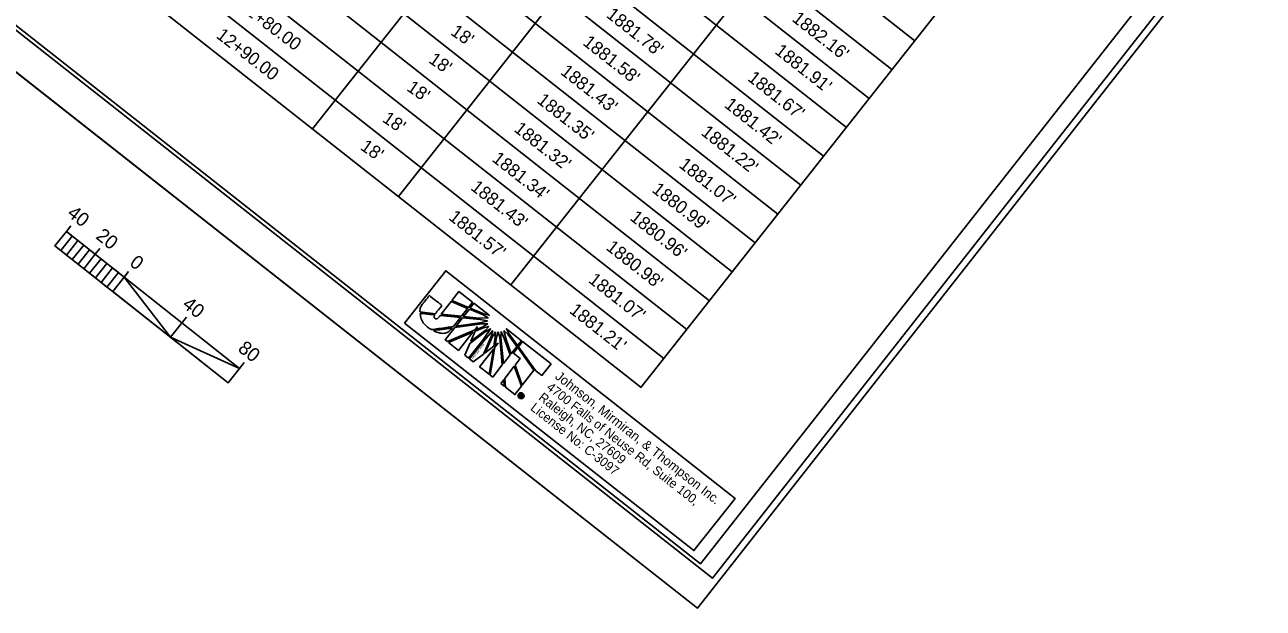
# Model space of a CAD drawing. Extents: x 556999 to 560450, y 504801 to 507732.
# Drawn here: x 557693 to 558366, y 506207 to 506524 of the extents above; entities that cross this region are included whole.
import ezdxf

# ---------------------------------------------------------------- set-up
doc = ezdxf.new("R2010")
doc.units = 0
for name, color, linetype in [('Prop Dimension', 7, 'Continuous'), ('Prop Horizontal Alignment Station Label', 7, 'Continuous'), ('Sheet Border Standard 30in CELL', 7, 'Continuous'), ('Sheet Cutting Line CELL', 7, 'Continuous'), ('Sheet Data Field CELL', 7, 'Continuous'), ('Sheet Plot Border Inside CELL', 7, 'Continuous'), ('Sheet Plot Border Outside CELL', 7, 'Continuous'), ('Sheet Title CELL', 7, 'Continuous')]:
    doc.layers.add(name, color=color, linetype=linetype)

msp = doc.modelspace()

# ---------------------------------------------------------------- linework, layer by layer
at = {"layer": 'Prop Dimension'}
for p, q in [((557928.5, 506379.09), (557924.67, 506374.2)), ((557935.87, 506373.31), (557928.5, 506379.09)), ((557924.23, 506373.64), (557918.84, 506366.78)), ((557933.22, 506369.93), (557924.23, 506373.64)), ((557924.67, 506374.2), (557933.64, 506370.46)), ((557933.64, 506370.46), (557935.87, 506373.31)), ((557936.66, 506372.74), (557934.59, 506370.1)), ((557944.95, 506366.24), (557936.66, 506372.74)), ((557918.84, 506366.78), (557929.87, 506365.66)), ((557930.51, 506364.9), (557926.91, 506360.31)), ((557929.87, 506365.66), (557933.22, 506369.93)), ((557940.08, 506363.95), (557930.51, 506364.9)), ((557934.14, 506369.53), (557931.02, 506365.55)), ((557931.02, 506365.55), (557939.29, 506364.71)), ((557941.65, 506366.39), (557934.14, 506369.53)), ((557934.59, 506370.1), (557942.1, 506366.96)), ((557939.29, 506364.71), (557944.29, 506364.79)), ((557944, 506363.17), (557940.08, 506363.95)), ((557944.29, 506364.79), (557941.65, 506366.39)), ((557942.1, 506366.96), (557944.95, 506366.24)), ((557926.3, 506359.53), (557921.05, 506352.85)), ((557922.26, 506351.89), (557936.82, 506358.05)), ((557935.99, 506356.99), (557922.84, 506351.45)), ((557941.01, 506361.65), (557926.3, 506359.53)), ((557926.91, 506360.31), (557941.01, 506362.3)), ((557928.33, 506347.14), (557935.99, 506356.99)), ((557942.79, 506357.28), (557934.47, 506350.96)), ((557935.03, 506352.17), (557942.71, 506358.02)), ((557937.32, 506357.52), (557935.03, 506352.17)), ((557936.82, 506358.05), (557938.34, 506359.99)), ((557941.77, 506359.41), (557937.32, 506357.52)), ((557938.34, 506359.99), (557937.66, 506358.37)), ((557937.66, 506358.37), (557941.4, 506359.97)), ((557941.01, 506362.3), (557944, 506363.17)), ((557944.15, 506361.62), (557941.01, 506361.65)), ((557941.4, 506359.97), (557944.15, 506361.62)), ((557941.41, 506352.79), (557945.65, 506358.85)), ((557944.7, 506360.13), (557941.77, 506359.41)), ((557946.87, 506357.9), (557941.93, 506352.38)), ((557942.71, 506358.02), (557944.7, 506360.13)), ((557945.65, 506358.85), (557942.79, 506357.28)), ((557945.99, 506354.78), (557946.87, 506357.9)), ((557948.3, 506357.3), (557946.7, 506354.75)), ((557948.26, 506354.31), (557948.3, 506357.3)), ((557949.86, 506357.14), (557948.91, 506354.07)), ((557950.64, 506354.09), (557949.86, 506357.14)), ((557951.42, 506357.35), (557951.25, 506354.2)), ((557953.15, 506353.69), (557951.42, 506357.35)), ((557952.96, 506357.98), (557954.07, 506353.03)), ((557955.01, 506355.91), (557952.96, 506357.98)), ((557962.47, 506352.43), (557954.33, 506358.87)), ((557954.33, 506358.87), (557955.63, 506356.28)), ((557921.05, 506352.85), (557922.26, 506351.89)), ((557922.84, 506351.45), (557928.33, 506347.14)), ((557934.47, 506350.96), (557931.69, 506344.56)), ((557933.7, 506342.98), (557941.41, 506352.79)), ((557941.93, 506352.38), (557934.23, 506342.57)), ((557941.76, 506345.04), (557945.99, 506354.78)), ((557946.7, 506354.75), (557942.77, 506345.82)), ((557947.46, 506349.36), (557948.26, 506354.31)), ((557949.72, 506351.07), (557948.03, 506348.92)), ((557948.91, 506354.07), (557948.19, 506349.9)), ((557948.19, 506349.9), (557949.72, 506351.07)), ((557952.02, 506339.22), (557950.64, 506354.09)), ((557951.25, 506354.2), (557952.62, 506339.99)), ((557956.32, 506344.7), (557953.15, 506353.69)), ((557954.07, 506353.03), (557956.84, 506345.36)), ((557959.95, 506349.22), (557955.01, 506355.91)), ((557955.63, 506356.28), (557960.39, 506349.78)), ((557960.39, 506349.78), (557962.47, 506352.43)), ((557963.07, 506352.02), (557960.84, 506349.17)), ((557978.55, 506339.87), (557963.07, 506352.02)), ((557931.69, 506344.56), (557933.7, 506342.98)), ((557936.27, 506340.96), (557941.76, 506345.04)), ((557947.2, 506347.86), (557939.68, 506338.28)), ((557942.77, 506345.82), (557947.46, 506349.36)), ((557944.96, 506334.14), (557947.2, 506347.86)), ((557948.03, 506348.92), (557945.53, 506333.63)), ((557952.62, 506339.99), (557956.32, 506344.7)), ((557956.84, 506345.36), (557959.95, 506349.22)), ((557960.39, 506348.6), (557958.06, 506345.64)), ((557958.06, 506345.64), (557961.84, 506342.67)), ((557960.43, 506348.65), (557960.39, 506348.6)), ((557969.28, 506336.44), (557960.43, 506348.65)), ((557960.84, 506349.17), (557960.77, 506349.09)), ((557960.77, 506349.09), (557970.28, 506336.11)), ((557934.23, 506342.57), (557936.27, 506340.96)), ((557939.68, 506338.28), (557944.96, 506334.14)), ((557946.84, 506332.61), (557952.02, 506339.22)), ((557958.59, 506338.53), (557953.42, 506331.94)), ((557962.45, 506327.74), (557958.59, 506338.53)), ((557961.84, 506342.67), (557959.06, 506339.13)), ((557959.06, 506339.13), (557962.9, 506328.31)), ((557973.57, 506333.52), (557978.55, 506339.87)), ((557945.53, 506333.63), (557946.84, 506332.61)), ((557952.86, 506331.22), (557951.23, 506329.16)), ((557953.14, 506327.66), (557952.86, 506331.22)), ((557953.42, 506331.94), (557953.87, 506327.09)), ((557962.9, 506328.31), (557969.28, 506336.44)), ((557970.28, 506336.11), (557973.57, 506333.52)), ((557951.23, 506329.16), (557953.14, 506327.66)), ((557953.87, 506327.09), (557958.87, 506323.17)), ((557958.87, 506323.17), (557962.45, 506327.74)), ((557961.35, 506322.34), (557962.23, 506323.47)), ((557962.23, 506323.47), (557962.69, 506323.11)), ((557962.69, 506323.11), (557962.53, 506322.89)), ((557962.53, 506322.89), (557962.69, 506323.11)), ((557962.69, 506323.11), (557962.77, 506323.05)), ((557963.22, 506323.77), (557963.03, 506323.54)), ((557963.03, 506323.54), (557963.22, 506323.77)), ((557961.47, 506321.54), (557961.27, 506321.29)), ((557961.27, 506321.29), (557961.47, 506321.54)), ((557961.28, 506321.29), (557961.27, 506321.29)), ((557961.61, 506322.14), (557961.35, 506322.34)), ((557961.47, 506321.54), (557961.48, 506321.53)), ((557961.95, 506322.58), (557961.61, 506322.14)), ((557962.16, 506322.42), (557961.95, 506322.58)), ((557962.32, 506323.05), (557962.11, 506322.79)), ((557962.11, 506322.79), (557962.32, 506322.62)), ((557962.32, 506322.62), (557962.16, 506322.42)), ((557962.16, 506322.42), (557962.32, 506322.62)), ((557962.17, 506322.41), (557962.16, 506322.42)), ((557962.53, 506322.89), (557962.32, 506323.05)), ((557962.32, 506322.62), (557962.33, 506322.62)), ((557962.56, 506322.87), (557962.53, 506322.89))]:
    msp.add_line(p, q, dxfattribs=at)
msp.add_lwpolyline([(557898.98, 506362.02), (558056.22, 506238.36), (558078.53, 506266.74), (557921.29, 506390.39)], close=True, dxfattribs=at)
for points in [[(557924.67, 506374.2), (557933.64, 506370.46), (557935.87, 506373.31), (557928.5, 506379.09), (557924.67, 506374.2)], [(557918.84, 506366.78), (557929.87, 506365.66), (557933.22, 506369.93), (557924.23, 506373.64), (557918.84, 506366.78)], [(557942.1, 506366.96), (557944.95, 506366.24), (557936.66, 506372.74), (557934.59, 506370.1), (557942.1, 506366.96)], [(557930.51, 506364.9), (557926.91, 506360.31), (557941.01, 506362.3), (557944, 506363.17), (557940.08, 506363.95), (557930.51, 506364.9)], [(557934.14, 506369.53), (557931.02, 506365.55), (557939.29, 506364.71), (557944.29, 506364.79), (557941.65, 506366.39), (557934.14, 506369.53)], [(557944.15, 506361.62), (557941.01, 506361.65), (557926.3, 506359.53), (557921.05, 506352.85), (557922.26, 506351.89), (557936.82, 506358.05), (557938.34, 506359.99), (557937.66, 506358.37), (557941.4, 506359.97), (557944.15, 506361.62)], [(557922.84, 506351.45), (557928.33, 506347.14), (557935.99, 506356.99), (557922.84, 506351.45)], [(557942.79, 506357.28), (557934.47, 506350.96), (557931.69, 506344.56), (557933.7, 506342.98), (557941.41, 506352.79), (557945.65, 506358.85), (557942.79, 506357.28)], [(557946.87, 506357.9), (557941.93, 506352.38), (557934.23, 506342.57), (557936.27, 506340.96), (557941.76, 506345.04), (557945.99, 506354.78), (557946.87, 506357.9)], [(557944.7, 506360.13), (557941.77, 506359.41), (557937.32, 506357.52), (557935.03, 506352.17), (557942.71, 506358.02), (557944.7, 506360.13)], [(557948.3, 506357.3), (557946.7, 506354.75), (557942.77, 506345.82), (557947.46, 506349.36), (557948.26, 506354.31), (557948.3, 506357.3)], [(557949.86, 506357.14), (557948.91, 506354.07), (557948.19, 506349.9), (557949.72, 506351.07), (557948.03, 506348.92), (557945.53, 506333.63), (557946.84, 506332.61), (557952.02, 506339.22), (557950.64, 506354.09), (557949.86, 506357.14)], [(557951.42, 506357.35), (557951.25, 506354.2), (557952.62, 506339.99), (557956.32, 506344.7), (557953.15, 506353.69), (557951.42, 506357.35)], [(557952.96, 506357.98), (557954.07, 506353.03), (557956.84, 506345.36), (557959.95, 506349.22), (557955.01, 506355.91), (557952.96, 506357.98)], [(557955.63, 506356.28), (557960.39, 506349.78), (557962.47, 506352.43), (557954.33, 506358.87), (557955.63, 506356.28)], [(557978.55, 506339.87), (557963.07, 506352.02), (557960.84, 506349.17), (557960.77, 506349.09), (557970.28, 506336.11), (557973.57, 506333.52), (557978.55, 506339.87)], [(557939.68, 506338.28), (557944.96, 506334.14), (557947.2, 506347.86), (557939.68, 506338.28)], [(557960.43, 506348.65), (557960.39, 506348.6), (557958.06, 506345.64), (557961.84, 506342.67), (557959.06, 506339.13), (557962.9, 506328.31), (557969.28, 506336.44), (557960.43, 506348.65)], [(557958.59, 506338.53), (557953.42, 506331.94), (557953.87, 506327.09), (557958.87, 506323.17), (557962.45, 506327.74), (557958.59, 506338.53), (557958.59, 506338.53)], [(557951.23, 506329.16), (557951.23, 506329.16), (557953.14, 506327.66), (557952.86, 506331.22), (557951.23, 506329.16)], [(557962.51, 506321.86), (557962.46, 506321.8), (557962.44, 506321.75), (557962.41, 506321.71), (557962.34, 506321.56), (557962.11, 506321.75)]]:
    msp.add_lwpolyline(points, dxfattribs=at)
for points, degree in [([(557919.21, 506371.59), (557919.21, 506371.59), (557912.39, 506376.94), (557912.39, 506376.94), (557912.39, 506376.94), (557909.04, 506372.68), (557909.04, 506372.68), (557909.04, 506372.68), (557908.69, 506372.23), (557908.69, 506372.23), (557907.64, 506370.89), (557907.25, 506369.49), (557907.33, 506368), (557907.33, 506368), (557915.6, 506367), (557915.67, 506367.09), (557915.67, 506367.09), (557919.21, 506371.59), (557919.21, 506371.59)], 3), ([(557915.45, 506364.63), (557915.01, 506364.97), (557914.83, 506365.51), (557915.31, 506366.45), (557915.31, 506366.45), (557907.45, 506367.33), (557907.45, 506367.33), (557907.74, 506364.34), (557909.54, 506361.28), (557911.74, 506359.55), (557912.31, 506359.1), (557912.78, 506358.81), (557913.49, 506358.45), (557913.49, 506358.45), (557925.5, 506360.1), (557925.5, 506360.1), (557925.5, 506360.1), (557929.39, 506365.05), (557929.39, 506365.05), (557929.39, 506365.05), (557918.36, 506366.16), (557918.36, 506366.16), (557916.9, 506364.3), (557916.06, 506364.15), (557915.45, 506364.63)], 3), ([(557915.45, 506364.63), (557915.01, 506364.97), (557914.83, 506365.51), (557915.31, 506366.45), (557915.31, 506366.45), (557907.45, 506367.33), (557907.45, 506367.33), (557907.74, 506364.34), (557909.54, 506361.28), (557911.74, 506359.55), (557912.31, 506359.1), (557912.78, 506358.81), (557913.49, 506358.45), (557913.49, 506358.45), (557925.5, 506360.1), (557925.5, 506360.1), (557925.5, 506360.1), (557929.39, 506365.05), (557929.39, 506365.05), (557929.39, 506365.05), (557918.36, 506366.16), (557918.36, 506366.16), (557916.9, 506364.3), (557916.06, 506364.15), (557915.45, 506364.63)], 3), ([(557924.89, 506359.32), (557924.89, 506359.32), (557914.51, 506357.9), (557914.51, 506357.9), (557917.86, 506356.39), (557922.11, 506356.06), (557924.89, 506359.32)], 3), ([(557961.27, 506321.29), (557960.93, 506321.56), (557960.73, 506321.91), (557960.68, 506322.35), (557960.62, 506322.78), (557960.73, 506323.17), (557961, 506323.52), (557961.28, 506323.87), (557961.63, 506324.07), (557962.05, 506324.1), (557962.49, 506324.15), (557962.87, 506324.04), (557963.22, 506323.77)], 3), ([(557963.03, 506323.54), (557962.76, 506323.75), (557962.45, 506323.84), (557962.11, 506323.81), (557961.76, 506323.77), (557961.47, 506323.61), (557961.25, 506323.33), (557961.03, 506323.05), (557960.94, 506322.73), (557960.98, 506322.38), (557961.03, 506322.03), (557961.19, 506321.76), (557961.47, 506321.54)], 3), ([(557961.48, 506321.53), (557961.75, 506321.31), (557962.06, 506321.22), (557962.41, 506321.26), (557962.75, 506321.31), (557963.05, 506321.47), (557963.27, 506321.75), (557963.48, 506322.02), (557963.57, 506322.35), (557963.53, 506322.7), (557963.48, 506323.03), (557963.32, 506323.31), (557963.03, 506323.54)], 3), ([(557963.22, 506323.77), (557963.56, 506323.5), (557963.76, 506323.14), (557963.83, 506322.71), (557963.89, 506322.3), (557963.78, 506321.9), (557963.51, 506321.55)], 3), ([(557963.51, 506321.55), (557963.24, 506321.21), (557962.88, 506321.01), (557962.45, 506320.95), (557962.02, 506320.9), (557961.63, 506321.01), (557961.28, 506321.29)], 3), ([(557962.11, 506321.75), (557962.13, 506321.83), (557962.15, 506321.91), (557962.22, 506321.99), (557962.3, 506322.09), (557962.34, 506322.16), (557962.33, 506322.22)], 3), ([(557962.33, 506322.22), (557962.31, 506322.26), (557962.27, 506322.33), (557962.17, 506322.41)], 2), ([(557962.33, 506322.62), (557962.49, 506322.49), (557962.61, 506322.47), (557962.68, 506322.57), (557962.75, 506322.65), (557962.71, 506322.75), (557962.56, 506322.87)], 3), ([(557962.6, 506322.23), (557962.64, 506322.14), (557962.61, 506322.01), (557962.51, 506321.86)], 2), ([(557962.77, 506323.05), (557963.05, 506322.82), (557963.11, 506322.6), (557962.93, 506322.37), (557962.85, 506322.27), (557962.74, 506322.22), (557962.6, 506322.23)], 3)]:
    msp.add_open_spline(points, degree=degree, dxfattribs=at)
at = {"layer": 'Prop Horizontal Alignment Station Label'}
for p, q in [((558238.26, 506960.32), (557848.96, 506467.44)), ((558284.85, 506923.51), (557895.63, 506430.73)), ((558346.16, 506875.79), (557956.7, 506382.71)), ((558416.82, 506819.98), (558027.36, 506326.9)), ((557902.16, 506730.92), (558176.24, 506515.39)), ((557889.77, 506715.23), (558163.84, 506499.69)), ((557877.37, 506699.53), (558151.44, 506484)), ((557864.97, 506683.84), (558139.05, 506468.3)), ((557852.58, 506668.14), (558126.65, 506452.61)), ((557840.18, 506652.45), (558114.25, 506436.91)), ((557827.78, 506636.75), (558101.86, 506421.22)), ((557815.39, 506621.06), (558089.46, 506405.52)), ((557802.99, 506605.36), (558077.06, 506389.83)), ((557790.59, 506589.67), (558064.67, 506374.13)), ((557778.2, 506573.97), (558052.27, 506358.44)), ((557765.8, 506558.28), (558039.87, 506342.74)), ((557753.4, 506542.58), (558027.48, 506327.05))]:
    msp.add_line(p, q, dxfattribs=at)
at = {"layer": 'Sheet Border Standard 30in CELL'}
msp.add_lwpolyline([(558579, 506891.48), (557635.74, 507633.27), (557116.49, 506972.99), (558059.75, 506231.2)], close=True, dxfattribs=at)
at = {"layer": 'Sheet Cutting Line CELL'}
msp.add_line((556999.11, 507039.85), (558058.08, 506207.07), dxfattribs=at)
at = {"layer": 'Sheet Data Field CELL'}
for p, q in [((557715.14, 506411.76), (557717.61, 506414.89)), ((557730.82, 506399.35), (557733.3, 506402.49)), ((557809.27, 506337.33), (557811.76, 506340.48))]:
    msp.add_line(p, q, dxfattribs=at)
at = {"layer": 'Sheet Plot Border Inside CELL'}
msp.add_lwpolyline([(558588.12, 506886.9), (557540.16, 507711.03), (557018.38, 507047.54), (558066.35, 506223.41)], close=True, dxfattribs=at)
at = {"layer": 'Sheet Plot Border Outside CELL'}
msp.add_lwpolyline([(558602.06, 506898.8), (557543.09, 507731.58), (556999.11, 507039.85), (558058.08, 506207.07)], close=True, dxfattribs=at)
at = {"layer": 'Sheet Title CELL'}
for p, q in [((557715.12, 506411.76), (557708.92, 506403.92)), ((557715.12, 506411.76), (557717.6, 506414.89)), ((557809.26, 506337.34), (557715.12, 506411.76)), ((557708.92, 506403.92), (557803.05, 506329.49)), ((557730.81, 506399.35), (557733.29, 506402.5)), ((557737.09, 506394.4), (557730.89, 506386.55)), ((557746.5, 506386.95), (557748.98, 506390.08)), ((557780.36, 506365.28), (557771.68, 506354.3)), ((557803.05, 506329.49), (557809.26, 506337.34)), ((557809.26, 506337.34), (557811.74, 506340.48))]:
    msp.add_line(p, q, dxfattribs=at)
for points in [[(557715.12, 506411.76), (557718.26, 506409.28), (557712.06, 506401.44), (557708.92, 506403.92)], [(557721.4, 506406.8), (557724.53, 506404.31), (557718.33, 506396.47), (557715.2, 506398.94)], [(557727.67, 506401.83), (557730.81, 506399.35), (557724.61, 506391.51), (557721.47, 506393.99)], [(557733.95, 506396.87), (557737.09, 506394.4), (557730.89, 506386.55), (557727.75, 506389.03)], [(557740.23, 506391.92), (557743.37, 506389.43), (557737.16, 506381.58), (557734.03, 506384.07)], [(557746.5, 506386.95), (557771.68, 506354.3), (557740.3, 506379.1)], [(557809.26, 506337.34), (557771.68, 506354.3), (557803.05, 506329.49)]]:
    msp.add_lwpolyline(points, close=True, dxfattribs=at)

# ---------------------------------------------------------------- texts
at = {"layer": 'Prop Dimension'}
for s, height, rotation, p in [('www.jmt.com', 1.2413, 231.81814, (557941.64, 506351)), ('Johnson, Mirmiran, & Thompson Inc.', 5.1112, 321.81814, (557980.33, 506332.2)), ('Raleigh, NC, 27609', 4.9652, 321.81814, (557971.31, 506320.73)), ('4700 Falls of Neuse Rd, Suite 100, ', 4.9652, 321.81814, (557975.69, 506326.31)), ('License No: C-3097', 4.9652, 321.81814, (557966.92, 506315.15))]:
    msp.add_text(s, height=height, rotation=rotation, dxfattribs=at).set_placement(p)
at = {"layer": 'Prop Horizontal Alignment Station Label'}
for s, rotation, p in [('12+80.00', 322.95133, (557808.09, 506533.27)), ("1881.78'", 321.77396, (558008.12, 506528.57)), ("1882.16'", 321.77396, (558109.03, 506526.46)), ('12+90.00', 322.35596, (557796.09, 506517.36)), ("18'", 325.49634, (557923.49, 506519.03)), ("1881.58'", 321.77396, (557995.32, 506513.54)), ("1881.91'", 321.77396, (558099.67, 506508.85)), ("18'", 325.49634, (557911.55, 506503.85)), ("1881.43'", 321.77396, (557983.22, 506497.65)), ("1881.67'", 321.77396, (558084.9, 506494.17)), ("18'", 325.49634, (557899.61, 506488.66)), ("1881.35'", 321.77396, (557970.42, 506482.08)), ("1881.42'", 321.77396, (558072.25, 506479.69)), ("18'", 325.49634, (557886.34, 506471.79)), ("1881.32'", 321.77396, (557957.93, 506466.56)), ("1881.22'", 321.77396, (558059.6, 506464.67)), ("18'", 325.49634, (557874.4, 506456.6)), ("1881.34'", 321.77396, (557945.99, 506450.31)), ("1881.07'", 321.77396, (558047.56, 506447.05)), ("1881.43'", 321.77396, (557934.37, 506434.85)), ("1880.99'", 321.77396, (558032.92, 506433.6)), ("1881.57'", 321.77396, (557922.44, 506418.62)), ("1880.96'", 321.77396, (558020.96, 506418.4)), ("1880.98'", 321.77396, (558007.98, 506402.24)), ("1881.07'", 321.77396, (557998.38, 506384.51)), ("1881.21'", 321.77396, (557988.05, 506367.98))]:
    msp.add_text(s, height=7, rotation=rotation, dxfattribs=at).set_placement(p)
at = {"layer": 'Sheet Title CELL'}
for s, p in [('40', (557715.06, 506420.63)), ('20', (557730.63, 506408.31)), ('0', (557748.99, 506393.77)), ('40', (557777.66, 506371.08)), ('80', (557807.87, 506347.16))]:
    msp.add_text(s, height=7.5, rotation=321.67144, dxfattribs=at).set_placement(p)

doc.saveas('drawing.dxf')
